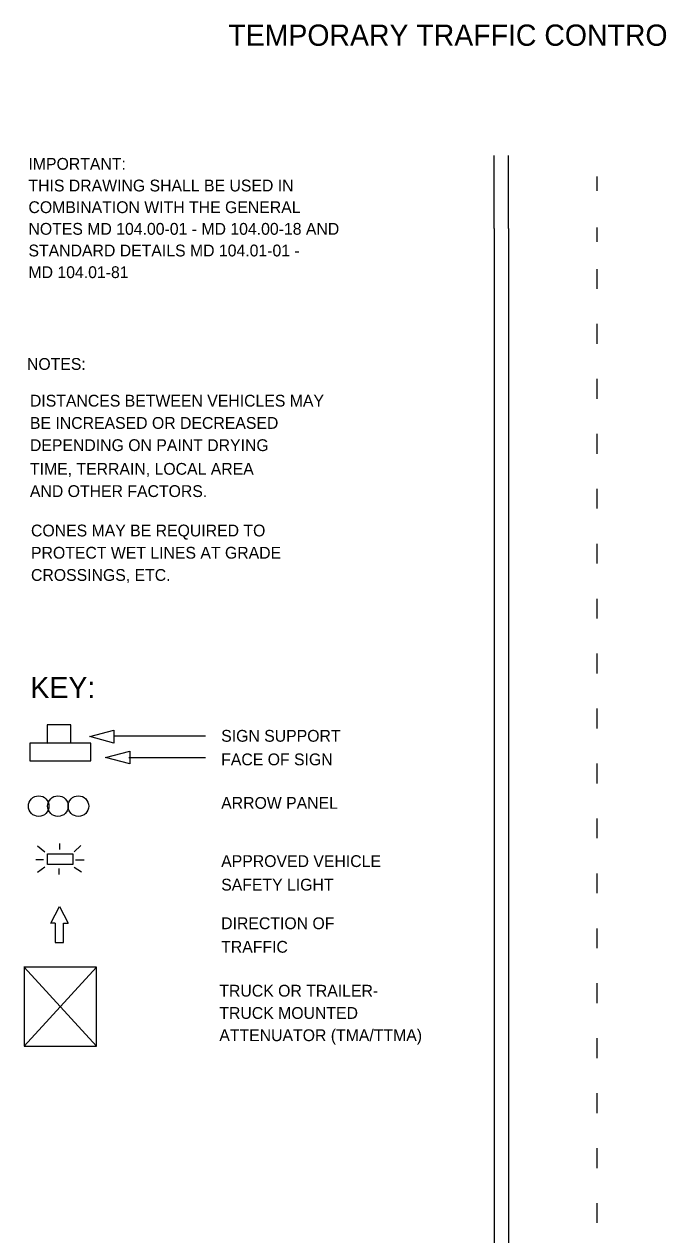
# Model space of a CAD drawing. Extents: x 1531.71 to 1538.58, y 1529.59 to 1539.48.
# Drawn here: x 1531.71 to 1534.93, y 1533.33 to 1539.48 of the extents above; entities that cross this region are included whole.
import ezdxf

# ---------------------------------------------------------------- set-up
doc = ezdxf.new("R2010")
doc.units = 0
for name, color, linetype in [('DETL-DIMS', 7, 'Continuous'), ('DETL-LINE', 7, 'Continuous'), ('DETL-NOTE', 7, 'Continuous'), ('DETL-TITL', 7, 'Continuous'), ('USER-BORD', 7, 'Continuous')]:
    doc.layers.add(name, color=color, linetype=linetype)

# ---------------------------------------------------------------- blocks, each defined once
blk = doc.blocks.new('BAR')
at = {"layer": 'USER-BORD'}
for p, q in [((-0.011, 0.0696), (-0.0512, 0.1025)), ((0.0695, 0.1172), (0.0695, 0.0842)), ((0.15, 0.0732), (0.1866, 0.1062)), ((-0.0183, 0.0293), (-0.0585, 0.0293)), ((0.0037, 0.0037), (0.0037, 0.0622)), ((0.0037, 0.0622), (0.1427, 0.0622)), ((0.1427, 0.0037), (0.0037, 0.0037)), ((0.1427, 0.0622), (0.1427, 0.0037)), ((0.1573, 0.0293), (0.2049, 0.0293)), ((-0.011, -0.011), (-0.0512, -0.0403)), ((0.0658, -0.0183), (0.0658, -0.0513)), ((0.15, -0.011), (0.1902, -0.0366))]:
    blk.add_line(p, q, dxfattribs=at)
blk = doc.blocks.new('SIGN13')
at = {"layer": 'USER-BORD'}
for points in [[(-0.0134, 0.0182), (0.011, 0.0189), (0.011, 0.0371), (-0.0134, 0.0371)], [(-0.0314, 0.0182), (-0.0314, 0), (0.032, 0), (0.032, 0.0182)]]:
    blk.add_lwpolyline(points, close=True, dxfattribs=at)

msp = doc.modelspace()

# ---------------------------------------------------------------- linework, layer by layer
at = {"layer": 'DETL-DIMS'}
for p, q in [((1532.1581, 1535.8641), (1532.626, 1535.8641)), ((1532.2368, 1535.7541), (1532.626, 1535.7541))]:
    msp.add_line(p, q, dxfattribs=at)
for points in [[(1532.0382, 1535.8604), (1532.1611, 1535.893), (1532.1611, 1535.8279)], [(1532.1185, 1535.7541), (1532.2414, 1535.7867), (1532.2414, 1535.7216)]]:
    msp.add_lwpolyline(points, close=True, dxfattribs=at)
at = {"layer": 'DETL-LINE'}
for p, q in [((1534.093, 1538.4412), (1534.093, 1538.8121)), ((1534.1643, 1538.4412), (1534.1643, 1538.8121)), ((1534.6162, 1538.6325), (1534.6162, 1538.7047)), ((1534.093, 1538.4412), (1534.093, 1531.4327)), ((1534.1643, 1538.4412), (1534.1643, 1531.4327)), ((1534.6162, 1538.3726), (1534.6162, 1538.4449)), ((1534.6162, 1538.134), (1534.6162, 1538.2349)), ((1534.6162, 1537.855), (1534.6162, 1537.9559)), ((1534.6162, 1537.5759), (1534.6162, 1537.6769)), ((1534.6162, 1537.2969), (1534.6162, 1537.3978)), ((1534.6162, 1537.0179), (1534.6162, 1537.1189)), ((1534.6162, 1536.7389), (1534.6162, 1536.8398)), ((1534.6162, 1536.4599), (1534.6162, 1536.5608)), ((1534.6162, 1536.1809), (1534.6162, 1536.2817)), ((1534.6162, 1535.9018), (1534.6162, 1536.0027)), ((1534.6162, 1535.6228), (1534.6162, 1535.7237)), ((1534.6162, 1535.3438), (1534.6162, 1535.4447)), ((1534.6162, 1535.0648), (1534.6162, 1535.1657)), ((1531.8404, 1534.9137), (1531.8847, 1534.9973)), ((1531.8847, 1534.9973), (1531.9294, 1534.9137)), ((1531.8621, 1534.9133), (1531.8396, 1534.9133)), ((1531.8621, 1534.9133), (1531.8621, 1534.8145)), ((1531.9044, 1534.8145), (1531.9044, 1534.9133)), ((1531.9044, 1534.9133), (1531.9294, 1534.9133)), ((1534.6162, 1534.7857), (1534.6162, 1534.8867)), ((1531.8621, 1534.8145), (1531.9044, 1534.8145)), ((1531.7053, 1534.6928), (1531.7053, 1534.2881)), ((1531.7053, 1534.6895), (1532.0727, 1534.2881)), ((1532.0727, 1534.6895), (1531.7053, 1534.2881)), ((1532.0727, 1534.6895), (1531.7053, 1534.6895)), ((1532.0727, 1534.2881), (1532.0727, 1534.6895)), ((1534.6162, 1534.5067), (1534.6162, 1534.6076)), ((1531.7053, 1534.2881), (1532.0727, 1534.2881)), ((1534.6162, 1534.2277), (1534.6162, 1534.3286)), ((1534.6162, 1533.9487), (1534.6162, 1534.0496)), ((1534.6162, 1533.6697), (1534.6162, 1533.7706)), ((1534.6162, 1533.3906), (1534.6162, 1533.4915))]:
    msp.add_line(p, q, dxfattribs=at)
for centre in [(1531.7789, 1535.5073), (1531.8767, 1535.5073), (1531.9805, 1535.5073)]:
    msp.add_circle(centre, 0.0523, dxfattribs=at)

# ---------------------------------------------------------------- block references
for name, p, xscale, yscale in [('SIGN13', (1531.8878, 1535.7377), 4.895646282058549, 4.895646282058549), ('BAR', (1531.8196, 1535.208), 0.930070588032, 0.930070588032)]:
    msp.add_blockref(name, p, dxfattribs=dict(at, xscale=xscale, yscale=yscale))

# ---------------------------------------------------------------- texts
at = {"layer": 'DETL-NOTE'}
for s, p in [('IMPORTANT:', (1531.7269, 1538.7388)), ('THIS DRAWING SHALL BE USED IN', (1531.7269, 1538.6288)), ('COMBINATION WITH THE GENERAL', (1531.7269, 1538.5188)), ('NOTES MD 104.00-01 - MD 104.00-18 AND', (1531.7269, 1538.4088)), ('STANDARD DETAILS MD 104.01-01 -', (1531.7269, 1538.2988)), ('MD 104.01-81', (1531.7269, 1538.1888)), ('NOTES:', (1531.7193, 1537.7227)), ('DISTANCES BETWEEN VEHICLES MAY', (1531.7344, 1537.5362)), ('BE INCREASED OR DECREASED', (1531.7344, 1537.4232)), ('DEPENDING ON PAINT DRYING', (1531.7344, 1537.3103)), ('TIME, TERRAIN, LOCAL AREA', (1531.7344, 1537.19)), ('AND OTHER FACTORS.', (1531.7344, 1537.077)), ('CONES MAY BE REQUIRED TO', (1531.7398, 1536.8769)), ('PROTECT WET LINES AT GRADE', (1531.7398, 1536.764)), ('CROSSINGS, ETC.', (1531.7398, 1536.6511)), ('SIGN SUPPORT', (1532.7058, 1535.8343)), ('FACE OF SIGN', (1532.7058, 1535.7147)), ('ARROW PANEL', (1532.7058, 1535.4937)), ('APPROVED VEHICLE', (1532.7058, 1535.1981)), ('SAFETY LIGHT', (1532.7058, 1535.0786)), ('DIRECTION OF', (1532.7058, 1534.8825)), ('TRAFFIC', (1532.7058, 1534.7629)), ('TRUCK OR TRAILER- ', (1532.6964, 1534.5399)), ('TRUCK MOUNTED', (1532.6964, 1534.4269)), ('ATTENUATOR (TMA/TTMA)', (1532.6964, 1534.3139))]:
    msp.add_text(s, height=0.06, dxfattribs=at).set_placement(p)
at = {"layer": 'DETL-TITL'}
for s, p in [('TEMPORARY TRAFFIC CONTROL TYPICAL APPLICATION', (1532.7424, 1539.3684)), ('KEY:', (1531.7372, 1536.0557))]:
    msp.add_text(s, height=0.108, dxfattribs=at).set_placement(p)

doc.saveas('drawing.dxf')
